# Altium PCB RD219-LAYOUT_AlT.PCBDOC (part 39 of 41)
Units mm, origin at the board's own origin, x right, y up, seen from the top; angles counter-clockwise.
Board outline 209.75 x 159.97 mm, 2 copper layers (TOP, BOTTOM), stack 0 mm thick; 398 components, 199 nets, 1469 pads, 0 vias.
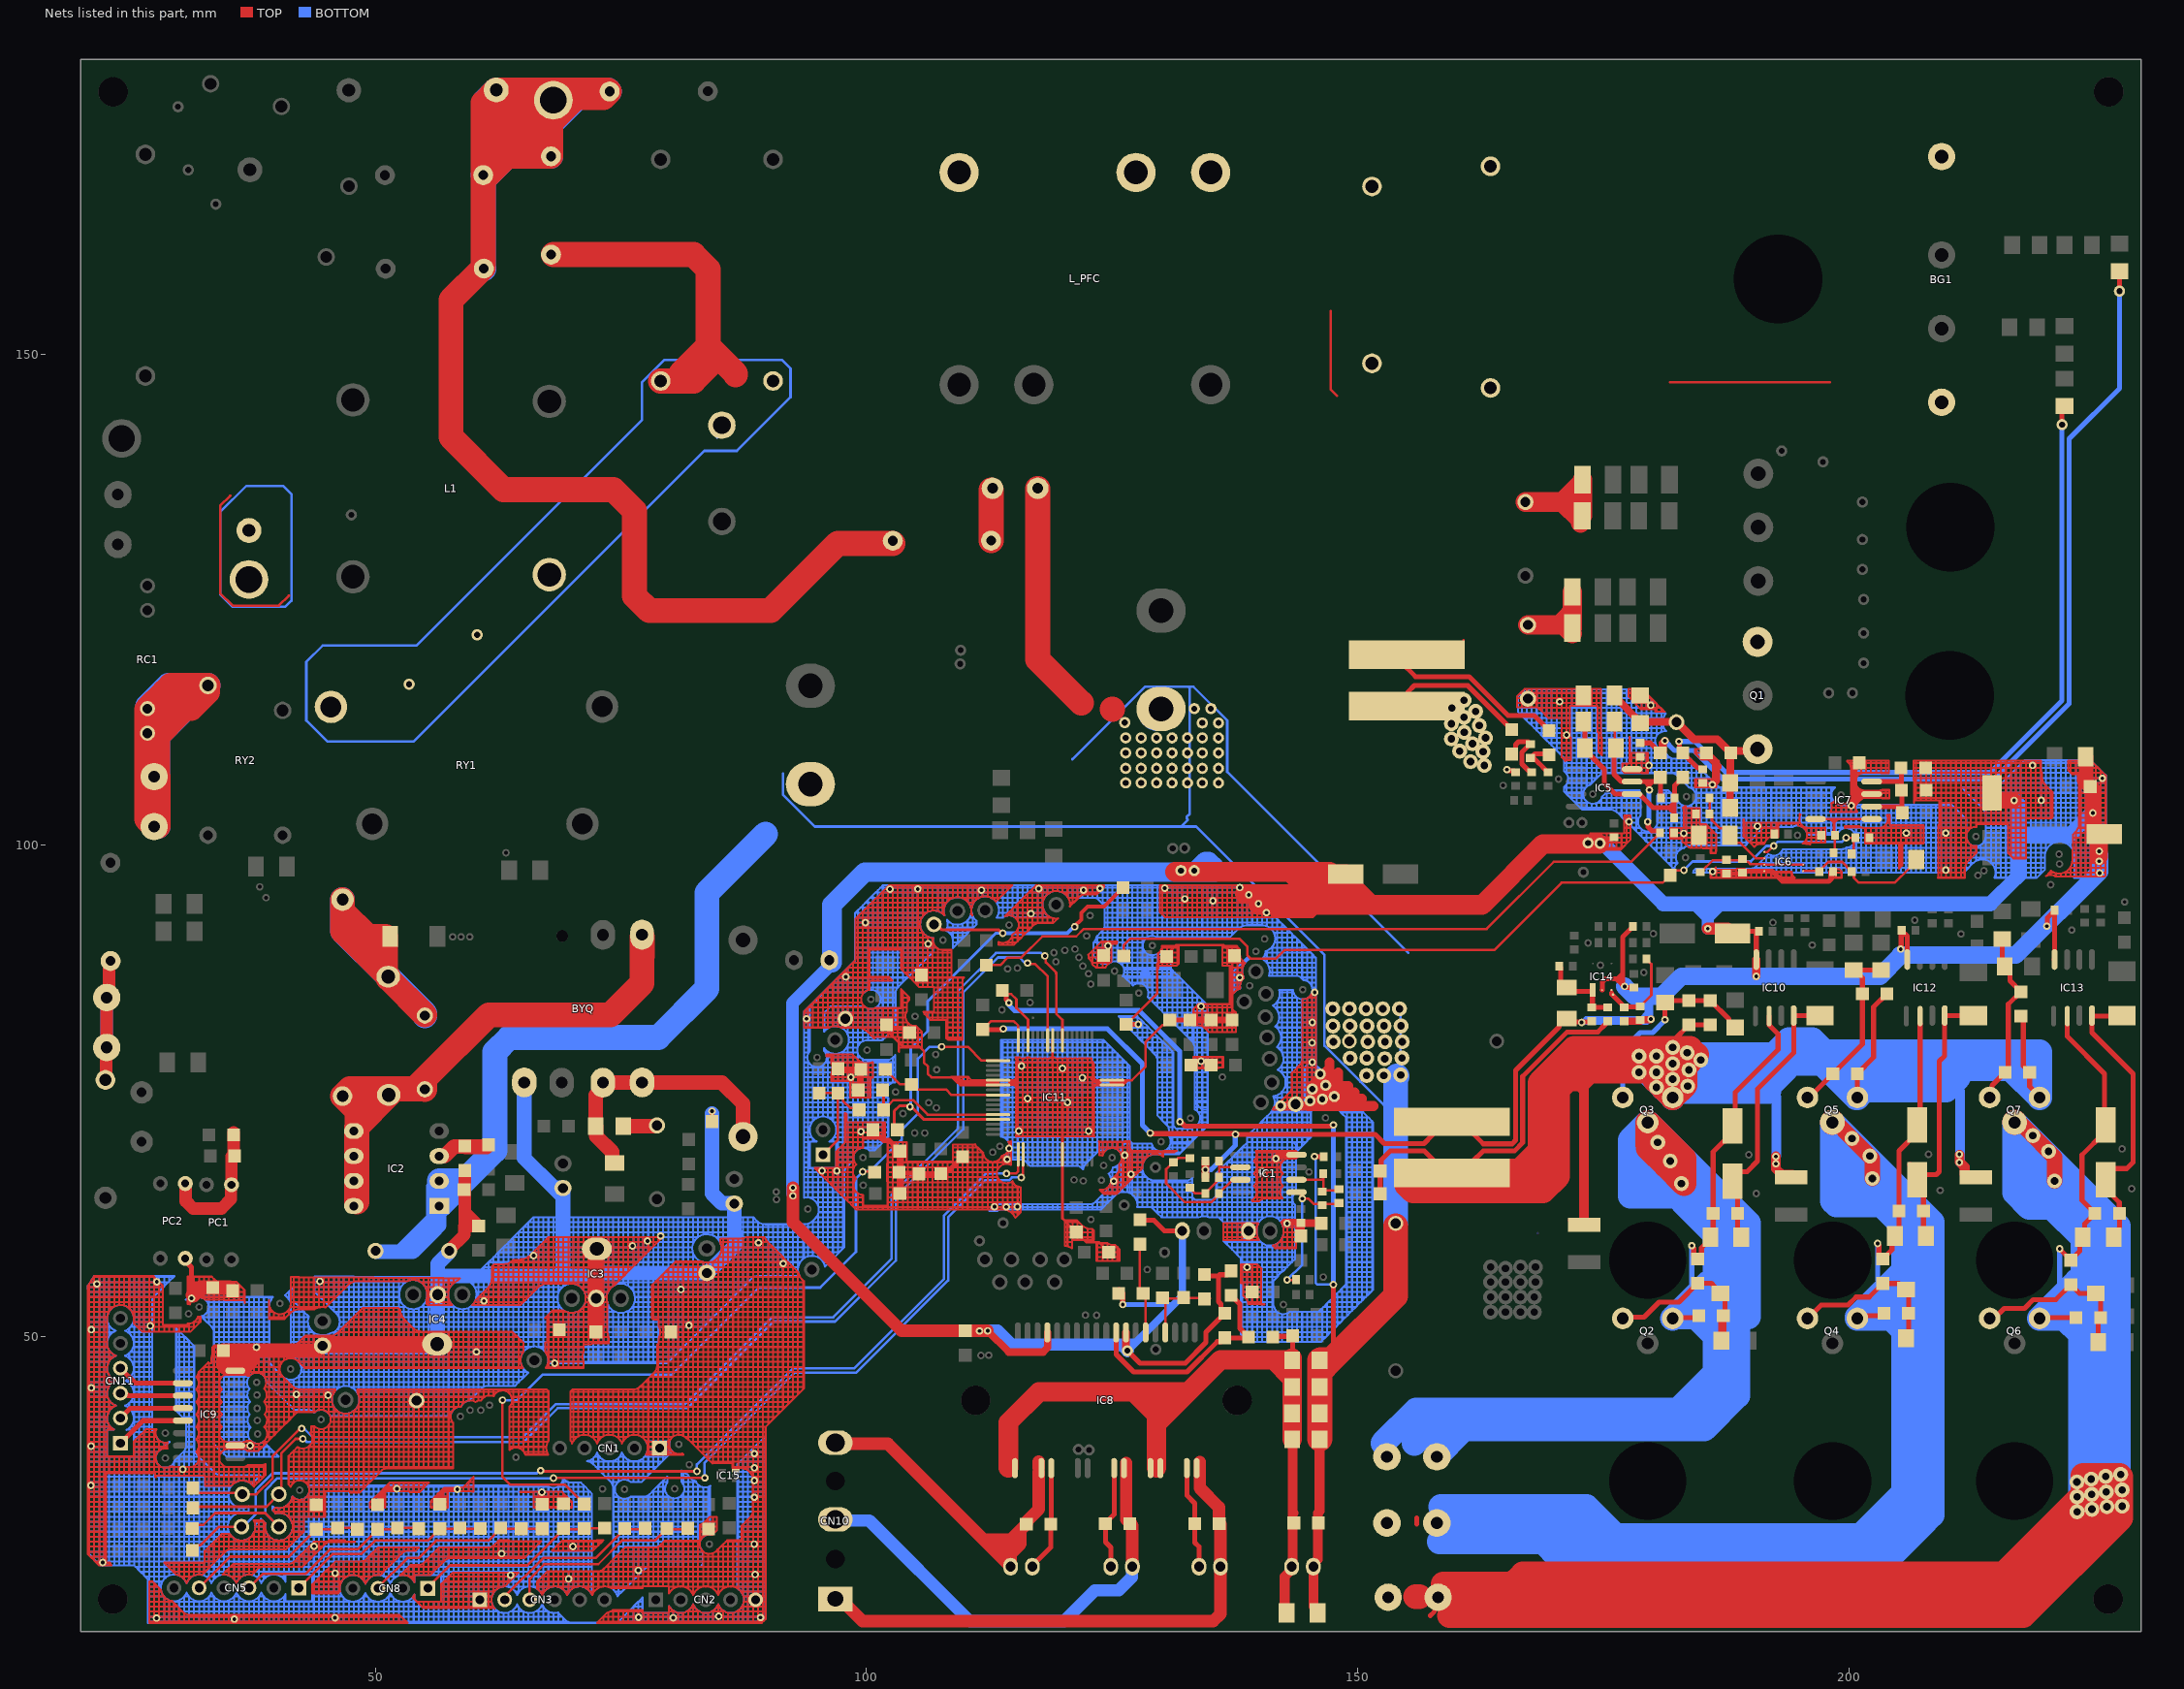
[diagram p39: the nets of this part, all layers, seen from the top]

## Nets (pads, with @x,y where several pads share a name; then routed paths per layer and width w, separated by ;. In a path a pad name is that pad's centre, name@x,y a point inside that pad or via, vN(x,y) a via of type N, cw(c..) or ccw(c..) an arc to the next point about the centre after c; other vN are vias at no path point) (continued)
GND: (continued)
  BOTTOM w1.2: 184.465,94.051 184.465,93.803 185.624,92.644 ; pad.@185.624,91.535 185.624,92.644 ; 185.624,93.908 185.624,92.644 ; 186.878,94.051 186.878,93.898 185.624,92.644
  BOTTOM w1.27: pad.@92.479,64.572 92.479,83.975 EC4.2@96.378,87.874 ; pad.@111.499,50.588 pad.@112.348,50.588 ; pad.@112.327,50.596 113.356,50.596 114.742,49.21 125.918,49.21 pad.@126.553,48.575
  BOTTOM w1.5: EC6.2@44.638,49.083 44.742,49.083 44.765,49.06 44.869,48.956 55.402,48.956 55.433,48.987 55.707,49.261 55.941,49.261 IC4.4@56.3,49.261 56.333,49.294 56.333,49.464 56.333,49.972 56.333,50.48 56.333,50.988 56.333,51.496 56.333,52.004 56.333,52.512 56.333,53.02 56.333,53.528 56.333,54.036 56.333,54.261 IC4.2@56.362,54.29 56.362,54.544 56.362,55.052 56.362,55.56 56.362,56.068 ; C63.1@50.032,58.735 50.122,58.645 52.766,58.645 ; C63.2@57.532,58.735 57.532,58.599 56.362,57.429 56.362,56.08 56.362,56.068 ; BYQ.5@65.161,75.88 65.161,68.184 68.191,65.154 ; IC3.2@72.491,53.909 72.52,53.938 72.52,54.036 72.52,54.544 72.52,55.052 72.52,55.56 72.52,56.068 72.52,56.195 ; IC3.4@72.553,58.938 72.52,58.905 72.52,58.608 72.52,58.1 72.52,57.592 72.52,57.084 72.52,56.576 72.52,56.195 ; pad.@84.262,72.705 84.262,64.577 85.268,63.572 86.512,63.572 EC18.2@86.541,63.543 86.541,62.164 86.541,61.656 86.541,61.148 86.541,60.691 86.592,60.64 86.592,60.132 86.592,59.624 86.592,59.263 86.445,59.116 86.421,59.092 85.937,58.608 85.913,58.584 85.781,58.453 85.429,58.1 85.405,58.076 84.921,57.592 84.897,57.569 84.413,57.084 84.389,57.061 84.29,56.962 83.905,56.576 83.881,56.553 83.818,56.489 EC5.2@83.754,56.489 83.373,56.489 82.865,56.489 82.357,56.489 81.849,56.489 81.341,56.489 80.833,56.489 80.325,56.489 79.817,56.489 79.309,56.489 78.801,56.489 78.293,56.489 77.785,56.489 77.277,56.489 76.769,56.489 76.261,56.489 75.753,56.489 75.245,56.489 74.737,56.489 74.229,56.489 73.721,56.489 73.213,56.489 72.814,56.489 72.705,56.38 72.52,56.195 ; EC4.2@96.229,87.747 96.229,87.847 EC4.2@96.327,87.945 ; pad.@173.432,100.248 174.629,100.248 pad.@174.657,100.219 174.916,100.219 181.084,94.051 184.465,94.051 185.481,94.051 186.878,94.051 214.386,94.051 217.044,96.708 217.295,96.959 217.295,97.216 217.295,97.724 217.295,98.232 217.295,98.74 217.295,99.248 217.295,99.756 217.295,100.264 217.295,100.772 217.295,101.153 ; pad.@216.85,104.582 216.977,104.455 217.104,104.328 217.295,104.137 217.295,103.82 217.295,103.312 217.295,102.804 217.295,102.296 217.295,101.788 217.295,101.28 217.295,101.153 ; pad.@224.851,103.439 224.724,103.312 224.597,103.185 224.216,102.804 224.089,102.677 223.708,102.296 223.581,102.169 223.2,101.788 223.073,101.661 222.692,101.28 222.565,101.153 222.057,101.153 221.549,101.153 221.041,101.153 220.533,101.153 220.025,101.153 219.517,101.153 219.009,101.153 218.501,101.153 217.993,101.153 217.485,101.153 217.295,101.153 ; 52.766,58.645 53.819,58.645 55.941,60.767 ; 52.766,58.645 52.766,58.862 55.941,62.037 ; 55.941,60.767 56.513,61.339 IC2.1@56.513,63.307 IC2.2@56.513,65.847 56.34,65.847 56.294,65.801 56.294,65.628 55.941,65.275 55.941,62.037 ; 55.941,60.767 55.941,62.037 ; 56.362,56.068 56.374,56.08 56.489,56.195 60.132,56.195 60.513,56.195 61.021,56.195 61.529,56.195 62.037,56.195 62.545,56.195 63.053,56.195 63.561,56.195 64.069,56.195 64.577,56.195 65.085,56.195 65.593,56.195 66.101,56.195 66.609,56.195 67.117,56.195 67.625,56.195 68.133,56.195 68.641,56.195 69.022,56.195 ; 68.191,65.154 69.076,65.154 EC3.2@69.105,65.125 69.105,64.24 ; 68.191,65.154 68.663,64.682 69.105,64.24 ; 69.022,56.195 69.149,56.195 69.657,56.195 70.165,56.195 70.673,56.195 71.181,56.195 71.689,56.195 72.197,56.195 72.52,56.195 ; 69.022,56.195 69.105,56.278 69.105,56.576 69.105,57.084 69.105,57.592 69.105,58.1 69.105,58.608 69.105,59.116 69.105,59.624 69.105,60.132 69.105,60.64 69.105,61.148 69.105,61.656 69.105,62.164 69.105,64.24
  BOTTOM w1.8: pad.@177.158,85.649 178.163,84.643 179.766,84.643 180.909,84.643 182.941,86.675 pad.@190.561,86.675 203.134,86.675 205.187,88.728 ; 205.187,88.834 216.977,88.834 225.486,97.343 225.486,97.851 225.486,98.232 225.486,98.74 225.486,98.994
  BOTTOM w2: EC4.2@96.476,88.072 96.476,93.936 99.824,97.283 pad.@133.411,97.283 ; pad.@133.411,97.283 135.443,97.283 135.443,97.724 134.808,98.359 134.487,98.359 pad.@133.411,97.283
  BOTTOM w2.54: IC2.1@56.513,63.307 59.053,65.847 ; IC2.2@56.513,65.847 59.053,65.847 ; 89.723,101.153 83.754,95.184 83.754,85.405 78.801,80.452 63.652,80.452 62.164,78.964 62.164,68.958 59.053,65.847 ; EC2.2@94.045,106.233 EC2.2@94.295,106.233 ; C90.1@153.858,61.536 153.858,76.388 pad.@153.871,76.4 ; pad.@153.982,76.511 pad.@153.985,76.508
  BOTTOM w4: EC2.2@94.295,106.233 EC2.2@94.391,106.329 ; EC1.2@129.636,113.655 129.867,113.886 EC1.2@129.982,113.886
HVMOS: C88.1 IC11.28 R142.2 | length 14.1
  TOP w0.254: C88.1@101.661,75.118 101.737,75.042 R142.2@101.737,73.086 ; R142.2@102.172,73.521 102.718,74.067 102.775,74.067 102.784,74.076 104.735,74.076 106.208,72.603 109.544,72.603 109.547,72.606 IC11.28@113.387,72.606
IAC_AD: C12.1 IC11.29 pad.@104.426,73.39 pad.@113.863,91.056 pad.@121.191,91.719 R9.2 TP5.1 | length 57.3
  TOP w0.3: C12.1@103.134,71.054 102.825,71.364 102.825,72.973 103.359,73.507 103.659,73.507 103.688,73.478 104.338,73.478 pad.@104.426,73.39 ; pad.@104.519,73.444 105.857,72.106 IC11.29@113.387,72.106 ; TP5.1@106.858,91.966 107.113,91.966 107.684,91.395 113.457,91.395 113.796,91.056 pad.@113.863,91.056
  TOP w0.4: pad.@121.191,91.719 121.191,91.78 121.854,92.443 121.854,93.152 122.489,93.787 124.191,93.787 R9.2@126.096,95.692
  BOTTOM w0.3: pad.@104.426,73.39 104.508,73.472 104.508,79.362 106.233,81.087 106.233,84.135 113.154,91.056 pad.@113.863,91.056
  BOTTOM w0.4: pad.@113.863,91.056 113.879,91.072 120.451,91.072 121.098,91.719 pad.@121.191,91.719
IGBT: C73.1 IC11.17 pad.@62.946,43.546 pad.@99.611,66.795 pad.@107.639,79.506 R79.2 | length 93.4
  TOP w0.254: pad.@62.946,43.546 62.946,35.728 63.734,34.94 69.31,34.94 R79.2@71.268,32.982 ; pad.@99.611,66.795 100.763,66.795 C73.1@100.823,66.736 C73.1@100.3,66.213 ; pad.@107.639,79.506 110.306,79.506 111.706,78.106 IC11.17@113.387,78.106
  BOTTOM w0.254: pad.@62.946,43.546 64.422,43.546 67.042,46.166 80.219,46.166 89.054,55.001 95.284,55.001 98.928,58.645 98.928,66.113 pad.@99.611,66.795 99.66,66.845 100.373,66.845 103.566,70.038 103.566,71.055 105.217,72.706 105.217,78.293 106.421,79.497 107.63,79.497 pad.@107.639,79.506
IGBT-Driver: C9.2 Q1.1 R43.1 R44.1 R135.1 TP10.1 ZD8.2 | length 23.8
  TOP w0.762: ZD8.2@176.137,115.25 176.137,115.05 176.556,114.631 176.68,114.631 177.496,113.815 177.496,113.791 178.231,113.056 178.231,112.872 178.65,112.453 R135.1@178.75,112.453 ; R44.1@187.891,103.693 187.89,103.694 187.891,103.696 R44.1@187.891,103.82 R43.1@187.891,106.36 ; R43.1@187.891,106.46 R43.1@187.891,106.36 ; R43.1@187.893,106.358 R43.1@187.891,106.36 ; C9.2@187.97,109.408 C9.2@187.972,109.409 ; Q1.1@190.688,109.257 Q1.1@190.688,109.789
  TOP w0.8: R135.1@178.75,112.453 178.88,112.583 181.163,112.583 ; 181.203,112.583 182.433,112.583 184.211,110.805 186.573,110.805 C9.2@187.97,109.408 187.931,109.368 187.931,106.4 R43.1@187.891,106.36 ; C9.2@187.972,109.409 188.161,109.599 190.498,109.599 Q1.1@190.688,109.789
IV+: C59.2 C94.2 C96.2 C101.2 C102.2 C103.2 pad.@178.623,76.896 pad.@178.623,78.547 pad.@180.401,75.372 pad.@180.401,76.896 pad.@180.401,78.547 pad.@182.043,76.203 pad.@182.052,77.785 pad.@182.052,79.436 pad.@183.523,78.888 pad.@183.576,75.499 pad.@183.703,77.15 pad.@184.913,78.156 pad.@192.545,68.338 pad.@192.553,67.597 pad.@211.223,68.554 pad.@211.226,67.742 Q3.3 Q5.3 Q7.3 R95.1 R99.1 R100.1 R103.1 R124.2 R131.2 R143.2 | length 359.5
  TOP w0.254: R100.1@152.277,64.548 R100.1@152.28,64.551
  TOP w0.508: R100.1@152.28,64.551 152.28,66.86 R99.1@152.283,66.863 152.375,66.955 152.375,67.977 153.312,68.915 156.759,68.915 R95.1@157.859,67.816 ; R95.1@161.732,67.879 162.748,68.895 165.94,68.895 166.782,69.737 166.782,76.479 171.317,81.014 174.425,81.014 175.252,81.842 175.252,81.957 175.398,82.103 R103.1@175.448,82.103 ; C101.2@171.639,61.843 172.085,61.397 C101.2@173.035,61.397 ; 173.035,76.134 173.924,77.023 ; pad.@182.052,78.384 182.062,78.374 pad.@182.367,78.374 ; pad.@182.052,79.436 182.246,79.63 182.246,80.265 C59.2@183.703,81.722 R124.2@185.862,81.722 ; Q5.3@200.848,74.348 C94.2@200.848,76.769 202.499,78.42 202.499,83.551 R131.2@203.845,84.897 R131.2@203.909,84.834 ; C103.2@212.028,66.345 C103.2@212.913,66.345 ; R143.2@217.739,82.738 217.739,77.531 C96.2@218.374,76.896 218.374,75.484 219.39,74.468 Q7.3@219.39,74.348 ; R95.1@157.181,66.676 R95.1@159.573,66.676 159.408,67.208 R95.1@157.181,66.676
  TOP w1: 170.316,75.193 170.622,75.499 172.527,75.499 ; C101.2@173.035,61.397 173.035,74.991 ; 173.035,76.134 173.035,75.499 ; 173.924,77.023 173.924,76.388 173.035,75.499 ; pad.@192.553,68.338 pad.@192.553,67.597 192.553,67.091 193.162,66.482 C102.2@194.244,66.482 ; pad.@211.262,68.514 211.262,67.774 211.763,67.273 211.763,66.545 211.963,66.345 C103.2@212.028,66.345 ; 172.527,75.499 173.035,75.499 ; 172.527,75.499 173.035,74.991 ; 173.035,74.991 173.035,75.499
  TOP w2.54: R95.1@155.001,65.466 155.636,64.831 166.379,64.831 ; R95.1@159.573,66.676 159.753,66.856 166.518,66.856 168.557,68.895 168.557,75.847 172.019,79.309 179.639,79.309 ; 169.292,74.169 170.316,75.193 170.316,68.768 ; 170.622,75.499 172.146,77.023 173.924,77.023 179.504,77.023 ; pad.@180.207,76.194 180.715,75.686 181.12,75.28 Q3.3@182.052,74.348 183.29,75.586 pad.@183.29,77.499 ; pad.@182.043,76.203 pad.@182.043,76.252 ; 166.379,64.831 170.316,68.768 ; 166.379,64.831 168.828,64.831 170.316,66.319 170.316,68.768 ; 179.639,79.309 pad.@180.401,78.547 182.043,76.905 pad.@182.043,76.252 ; 179.639,79.309 pad.@181.671,79.309 ; pad.@181.671,79.309 183.83,79.309 184.465,78.674 pad.@183.29,77.499 ; pad.@181.671,79.309 183.29,77.69 pad.@183.29,77.499 ; pad.@182.043,76.252 pad.@183.29,77.499
  BOTTOM w0.508: 191.835,74.991 191.835,74.987 192.422,74.4
  BOTTOM w1: pad.@192.545,68.338 pad.@192.563,68.338 ; pad.@192.563,67.628 pad.@192.563,68.338 ; 192.593,74.356 192.593,68.403 192.563,68.373 pad.@192.563,68.338 ; pad.@211.295,67.742 211.295,74.958 211.135,75.118 211.135,76.388 212.024,77.277
  BOTTOM w2.54: pad.@180.401,76.896 182.306,76.896 182.521,76.681 182.878,76.325 183.453,75.749 184.85,77.146 ; 185.646,77.942 185.387,77.683 184.85,77.146 ; 199.32,77.146 199.642,77.468 200.848,76.261 ; 211.135,76.388 209.865,75.118 201.618,75.118 Q5.3@200.848,74.348 ; 184.85,77.146 192.949,77.146 193.21,76.885 ; 192.339,78.674 194.999,78.674 ; 192.339,78.674 193.863,80.198 196.268,80.198 197.502,78.964 ; 192.339,78.674 180.147,78.674 179.385,77.912 179.385,77.015 181.12,75.28 Q3.3@182.052,74.348 182.695,74.991 191.835,74.991 191.835,75.51 193.21,76.885 ; 193.21,76.885 194.177,77.852 ; 194.177,77.852 197.221,77.852 200.725,74.348 Q5.3@200.848,74.348 ; 194.177,77.852 194.999,78.674 ; 194.999,78.674 197.792,78.674 ; 197.502,78.964 219.39,78.964 219.39,76.515 ; 197.502,78.964 197.792,78.674 ; 197.792,78.674 217.231,78.674 218.565,77.341 ; Q5.3@200.848,74.348 200.848,76.261 ; 200.848,76.261 201.229,76.261 202.245,77.277 212.024,77.277 216.461,77.277 ; 216.461,77.277 Q7.3@219.39,74.348 219.39,76.515 ; 216.461,77.277 218.501,77.277 218.565,77.341 ; 218.565,77.341 219.39,76.515
LED1: IC11.33 pad.@66.833,36.376 pad.@82.737,36.311 pad.@114.245,66.61 R67.2 TP12.1 | length 107.4
  TOP w0.254: R67.2@31.379,28.255 31.892,28.768 32.197,28.768 34.097,30.668 TP12.1@36.383,30.668 ; pad.@66.833,36.376 66.909,36.3 82.726,36.3 pad.@82.737,36.311 ; pad.@114.245,66.61 115.189,66.61 115.437,66.858 IC11.33@115.437,68.556
  BOTTOM w0.254: TP12.1@36.423,30.541 37.844,31.962 37.844,34.415 39.532,36.103 66.43,36.103 66.704,36.376 pad.@66.833,36.376 ; pad.@82.737,36.311 82.737,37.003 88.63,42.897 92.503,46.77 98.75,46.77 107.884,55.904 107.884,62.346 112.148,66.61 pad.@114.245,66.61
LED2: IC11.34 pad.@68.133,35.618 pad.@83.551,35.642 pad.@115.751,66.202 R68.2 TP13.1 | length 111.6
  TOP w0.254: R68.2@31.367,30.478 31.741,30.852 32.503,30.852 33.716,32.065 38.796,32.065 TP13.1@40.193,30.668 ; pad.@68.133,35.618 68.145,35.63 83.539,35.63 pad.@83.551,35.642 ; pad.@115.751,66.202 115.751,66.34 115.937,66.526 IC11.34@115.937,68.556
  BOTTOM w0.254: TP13.1@40.193,30.668 38.796,32.065 38.796,34.351 40.04,35.595 68.11,35.595 pad.@68.133,35.618 ; pad.@83.551,35.642 83.5,35.694 83.5,37.156 89.062,42.718 92.682,46.338 98.929,46.338 108.316,55.725 108.316,62.167 112.073,65.924 114.529,65.924 114.807,66.202 pad.@115.751,66.202
LED3: IC11.10 pad.@40.701,33.97 pad.@42.625,39.609 pad.@116.388,88.026 R69.2 TP14.1 | length 132.1
  TOP w0.254: R69.2@31.43,32.573 31.557,32.7 38.923,32.7 TP14.1@40.193,33.97 40.447,34.224 40.447,38.161 41.895,39.609 pad.@42.625,39.609 ; pad.@116.388,88.026 116.471,87.943 117.15,87.943 118.437,86.656 IC11.10@118.437,80.156
  BOTTOM w0.254: pad.@42.625,39.609 42.723,39.609 43.028,39.304 65.133,39.304 68.562,42.733 81.746,42.733 90.558,51.545 96.788,51.545 102.98,57.737 102.98,64.245 109.853,71.118 109.853,85.064 113.381,88.592 115.574,88.592 116.043,88.123 116.291,88.123 pad.@116.388,88.026
LED4: IC11.7 pad.@42.513,40.658 pad.@118.147,88.757 R70.2 TP15.1 | length 133.3
  TOP w0.254: R70.2@31.43,34.605 31.938,34.097 36.336,34.097 TP15.1@36.463,33.97 37.907,33.97 39.558,35.621 39.558,37.872 42.247,40.561 42.415,40.561 pad.@42.513,40.658 ; pad.@118.147,88.757 118.245,88.66 118.245,88.101 119.301,87.045 119.301,86.942 119.303,86.94 119.303,82.876 119.937,82.242 IC11.7@119.937,80.156
  BOTTOM w0.254: pad.@42.513,40.658 42.61,40.561 42.86,40.561 43.66,39.761 64.979,39.761 68.375,43.157 81.552,43.157 90.372,51.977 96.609,51.977 102.548,57.916 102.548,64.424 109.309,71.185 109.309,85.179 113.179,89.049 117.745,89.049 118.037,88.757 pad.@118.147,88.757
NetAC-L_1: AC_L.1 F1.1 | length 54.2
  TOP w0.254: 35.24,135.57 34.224,134.554 34.224,125.664 35.494,124.394 40.193,124.394 41.209,125.41
  BOTTOM w0.254: 34.224,125.537 35.494,124.267 40.828,124.267 41.463,124.902 41.463,135.697 41.485,135.719 40.618,136.586 36.891,136.586 34.224,133.919 34.224,125.537
NetBG1_1: BG1.1 C8.1 L_PFC.1 L_PFC.2 L_PFC.3 Z2.1
NetBG1_4: BG1.4 C8.2 R1.2 R2.1 Z2.2 | length 50.9
  TOP w0.254: 147.254,154.366 147.254,146.365 147.889,145.73 ; R1.2@155.065,119.328 R1.2@155.711,119.328 ; R1.2@159.258,119.39 159.457,119.39 160.778,120.711 160.778,120.859 ; C8.2@163.51,146.545 C8.2@163.838,146.873 ; 181.798,147.127 198.054,147.127
  TOP w0.5: R1.2@154.979,118.066 155.876,117.169 161.337,117.169 165.288,113.218 167.955,113.218 R2.1@169.479,111.694 ; R1.2@155.005,119.388 R1.2@155.065,119.328 ; R1.2@155.711,119.39 R1.2@158.299,119.39 ; R1.2@159.258,119.39 R1.2@158.299,119.39 ; R1.2@159.446,118.243 R1.2@158.299,119.39
NetBYQ_1: BYQ.1 C25.2 D6.2 IC2.5 IC2.6 IC2.7 IC2.8 R19.2 | length 59
  TOP w2.54: IC2.8@48.103,63.702 48.103,65.847 IC2.5@48.103,71.344 ; IC2.5@48.175,71.183 IC2.5@48.175,71.416 ; BYQ.1@77.163,90.663 77.163,88.751 77.15,88.738 77.15,85.951 73.95,82.751 61.546,82.751 55.052,76.257 ; IC2.5@48.175,71.416 D6.2@51.369,74.61 D6.2@51.988,75.229 ; IC2.5@48.175,71.416 48.175,72.978 R19.2@46.67,74.483 47.416,75.229 D6.2@51.988,75.229 ; D6.2@51.988,75.229 54.025,75.229 ; 54.025,75.229 55.001,75.229 C25.2@55.052,75.178 55.052,76.257 ; 54.025,75.229 54.513,75.717 55.052,76.257
NetBYQ_7: BYQ.7 BYQ.8 D4.1 D5.1 R134.2 | length 27.6
  TOP w1.27: BYQ.8@77.137,75.867 BYQ.8@77.15,75.88
  TOP w1.5: D5.1@74.356,67.879 74.106,68.129 74.106,68.803 72.498,70.411 72.498,71.385 R134.2@72.448,71.435 72.448,74.593 73.162,75.308 BYQ.7@73.162,75.855 73.175,75.867 BYQ.8@77.137,75.867 ; BYQ.8@77.15,75.88 85.278,75.88 87.437,73.721 D4.1@87.437,70.358
NetC2_1: C2.1 C6.2 C7.1 L1.4 pad.@53.446,116.399 pad.@60.367,121.42 pad.@84.784,141.512 PTC.1 RY1.2 | length 181
  TOP w2.54: C6.2@68.148,160.114 82.393,160.114 83.881,158.626 83.881,150.81 ; C2.1@79.055,147.254 81.087,147.254 ; 86.675,147.889 86.675,148.016 83.881,150.81 ; 81.087,147.254 82.393,147.254 83.881,148.742 83.881,150.81 ; 81.087,147.254 81.087,148.016 83.881,150.81
  BOTTOM w0.254: PTC.1@84.854,141.643 85.549,142.338 85.696,142.338 85.696,142.485 PTC.1@86.454,143.243 ; 42.987,112.71 45.146,110.551 53.909,110.551 83.5,140.142 86.802,140.142 92.263,145.603 92.263,148.524 91.374,149.413 79.436,149.413 77.15,147.127 77.15,143.317 54.163,120.33 44.638,120.33 42.987,118.679 42.987,112.71
NetC3_1: C3.1 C4.1 C5.1 C6.1 C61.1 GND_EARTH.1 pad.@62.307,176.87 SA1.1 | length 249.1
  TOP w2.54: C3.1@60.903,158.693 57.719,155.509 57.719,141.539 63.053,136.205 74.229,136.205 76.388,134.046 76.388,125.374 77.876,123.886 90.231,123.886 97.076,130.731 C61.1@102.677,130.731 ; C3.1@60.988,158.759 60.988,168.205 C4.1@60.99,168.207 60.99,175.553 pad.@62.307,176.87 ; C4.1@61.496,168.222 63.082,169.807 63.082,170.421 ; 62.307,170.114 pad.@62.307,176.87 ; GND_EARTH.1@67.879,175.575 67.866,175.562 67.866,173.543 ; pad.@62.307,176.87 pad.@63.082,176.096 ; pad.@62.307,176.87 73.696,176.87 C5.1@73.848,176.718 73.226,176.096 70.419,176.096 ; 63.082,170.421 63.388,170.114 64.831,170.114 ; 63.082,170.421 pad.@63.082,176.096 ; pad.@63.082,176.096 64.704,176.096 ; 64.704,176.096 GND_EARTH.1@66.228,176.096 ; 64.704,176.096 64.704,170.241 64.831,170.114 ; 64.831,170.114 66.228,170.114 ; 66.228,170.114 C6.1@67.879,170.114 67.879,171.738 67.866,171.752 ; 66.228,170.114 67.054,170.94 67.866,171.752 ; 66.228,170.114 GND_EARTH.1@66.228,176.096 ; GND_EARTH.1@66.228,176.096 67.866,176.096 GND_EARTH.1@68.133,175.829 ; 67.866,171.752 67.866,173.543 ; 67.866,173.543 69.142,174.82 70.419,176.096 ; GND_EARTH.1@68.133,175.829 68.511,175.829 GND_EARTH.1@68.778,176.096 ; GND_EARTH.1@68.133,175.829 68.4,176.096 GND_EARTH.1@68.778,176.096 ; GND_EARTH.1@68.778,176.096 70.419,176.096
  BOTTOM w2.54: C4.1@60.99,168.207 C4.1@61.021,168.176 ; C3.1@61.054,158.693 61.021,158.727 C4.1@61.021,168.176 ; 61.496,171.602 61.496,168.222 63.592,170.318 ; C4.1@61.021,168.176 61.021,175.584 pad.@62.307,176.87 ; pad.@62.307,176.87 62.981,176.197 64.323,176.197 ; pad.@62.307,176.87 62.307,171.602 63.592,170.318 ; pad.@62.307,176.87 73.696,176.87 C5.1@73.848,176.718 71.181,176.718 71.054,176.591 ; 63.592,170.318 64.323,171.049 64.323,176.197 ; 63.592,170.318 63.795,170.114 65.72,170.114 ; 64.323,176.197 GND_EARTH.1@66.777,176.197 ; 65.72,170.114 C6.1@67.879,170.114 67.879,173.543 ; 65.72,170.114 66.777,171.171 GND_EARTH.1@66.777,176.197 ; GND_EARTH.1@66.777,176.197 66.878,176.096 67.866,176.096 GND_EARTH.1@68.133,175.829 ; 67.879,173.543 68.006,173.543 71.054,176.591 ; 67.879,173.543 67.879,175.575 GND_EARTH.1@68.133,175.829 ; GND_EARTH.1@68.133,175.829 68.511,175.829 69.273,176.591 71.054,176.591
NetC10_1: C10.1 R38.1 R40.1 | length 15.2
  TOP w2: C10.1@167.066,134.935 170.846,134.935 ; R38.1@172.598,134.924 172.587,134.935 170.846,134.935 ; R38.1@172.678,132.829 172.678,133.103 170.846,134.935 ; R38.1@172.856,133.538 172.869,133.551 R40.1@172.869,136.958 ; 170.846,134.935 R40.1@172.869,136.958 ; R40.1@172.869,136.958 172.882,136.971 R40.1@172.882,137.221 172.869,137.208 R40.1@172.869,136.958
NetC11_1: C11.1 R3.2 R4.1 | length 6.6
  TOP w0.508: R3.2@165.669,109.281 166.058,109.67 166.058,110.253 166.356,110.551 167.32,110.551 C11.1@167.574,110.297 ; C11.1@167.524,110.297 166.956,109.729 166.945,109.729 166.692,109.476 166.692,108.289 167.394,107.587 167.555,107.587 R4.1@167.701,107.441
NetC11_2: C11.2 R2.2 R5.1 | length 4.5
  TOP w0.5: C11.2@167.574,108.897 167.624,108.897 168.036,109.309 169.375,109.309 R2.2@169.479,109.205
  TOP w0.508: C11.2@167.574,108.897 167.72,108.751 168.04,108.751 168.399,108.392 168.401,108.392 169.156,107.637 169.156,107.587 169.302,107.441 R5.1@169.352,107.441
NetC13_2: C13.2 D7.2 IC6.2 R10.1 | length 9.4
  TOP w0.254: R10.1@185.8,104.836 C13.2@185.8,103.185 186.046,102.939 186.046,102.55 186.843,101.753 187.202,101.753 D7.2@187.875,101.08 ; D7.2@187.875,101.026 187.875,100.94 188.548,100.267 188.907,100.267 190.49,98.684 IC6.2@191.38,98.684
NetC14_2: C14.2 IC6.3 IC6.6 R13.1 R14.2 | length 11.2
  TOP w0.254: R13.1@184.973,97.34 186.119,98.486 187.462,98.486 R14.2@187.506,98.53 187.55,98.486 189.039,98.486 C14.2@189.169,98.616 189.442,98.343 189.688,98.343 189.924,98.107 191.307,98.107 IC6.3@191.38,98.034 IC6.6@195.33,98.034
NetC17_2: C17.2 IC6.1 pad.@183.195,97.47 pad.@192.336,99.942 pad.@199.705,100.772 pad.@200.656,100.772 R15.1 R17.1 R18.1 | length 85.4
  TOP w0.254: R17.1@126.174,88.726 126.174,89.85 126.809,90.485 137.983,90.485 138.745,89.723 138.745,88.834 139.126,88.453 141.666,88.453 142.555,89.342 163.891,89.342 170.749,96.2 181.036,96.2 R18.1@181.798,96.962 182.306,97.47 pad.@183.195,97.47 ; IC6.1@191.38,99.334 191.705,99.334 192.313,99.942 pad.@192.336,99.942 ; pad.@199.705,100.772 C17.2@200.435,100.772 ; R15.1@200.275,99.121 200.467,99.313 200.467,100.583 C17.2@200.656,100.772 C17.2@200.435,100.772 ; C17.2@200.467,100.804 C17.2@200.435,100.772
  BOTTOM w0.254: pad.@183.195,97.47 184.084,98.359 190.002,98.359 191.585,99.942 pad.@192.336,99.942 ; pad.@192.322,99.956 192.709,100.342 199.275,100.342 pad.@199.705,100.772
NetC18_2: C18.2 D8.1 IC6.5 R16.2 | length 15
  TOP w0.254: IC6.5@195.33,97.384 196.932,97.384 C18.2@196.973,97.343 196.973,97.393 197.246,97.666 197.249,97.666 197.899,98.316 199.29,98.316 200.213,97.393 R16.2@200.213,97.293 ; R16.2@200.275,97.343 200.494,97.124 200.494,96.681 200.975,96.2 204.663,96.2 206.16,97.697 206.833,98.37 D8.1@206.833,98.57 ; D8.1@206.779,98.624 D8.1@206.96,98.805 ; D8.1@206.869,98.534 206.96,98.624 D8.1@206.96,98.805 ; D8.1@206.96,98.824 D8.1@206.96,98.805 ; D8.1@207,98.792 D8.1@207.091,98.882 ; D8.1@207.037,98.882 D8.1@206.96,98.805
NetC20_2: C20.2 IC7.2 IC7.4 R41.2 R42.2 | length 11.7
  TOP w0.254: R41.2@204.897,102.789 R41.2@205.42,103.312 R41.2@205.382,103.35
  TOP w0.5: IC7.4@202.301,106.487 205.318,106.487 ; IC7.2@202.32,103.928 IC7.2@202.301,103.947 R41.2@205.293,103.947 ; R41.2@205.039,103.693 R41.2@205.293,103.693 ; R42.2@205.293,107.884 205.318,107.859 205.318,106.487 ; R41.2@205.382,103.35 205.382,105.56 C20.2@205.344,105.598 205.318,105.623 205.318,106.487
NetC22_1: C22.1 IC2.3 R21.1 | length 5.1
  TOP w1.5: IC2.3@56.513,68.387 56.532,68.406 57.103,68.406 58.046,69.349 C22.1@59.062,69.349 ; C22.1@59.185,69.334 R21.1@61.333,69.334
NetC25_1: C25.1 D3.1 D6.1 R19.1 | length 41.2
  TOP w2.54: R19.1@46.67,94.483 46.67,93.274 ; D6.1@51.196,86.636 D6.1@51.324,86.636 ; D6.1@51.324,86.466 C25.1@55.052,82.738 ; 46.67,93.274 49.21,90.734 ; 46.67,93.274 46.67,91.29 47.226,90.734 ; 47.226,90.734 51.022,86.938 51.022,90.734 49.21,90.734 ; 47.226,90.734 49.21,90.734
  BOTTOM w2.54: R19.1@46.67,94.483 46.67,91.29 D6.1@51.324,86.636 55.052,82.908 C25.1@55.052,82.678
NetC26_2: C26.2 pad.@182.69,110.567 pad.@221.676,142.809 R25.2 R29.1 | length 77.4
  TOP w0.508: pad.@182.69,110.567 182.738,110.518 182.738,109.738 R29.1@183.068,109.408 184.584,107.892 184.954,107.892 C26.2@185.1,107.746 ; pad.@221.676,142.809 221.676,144.454 R25.2@221.93,144.708
  BOTTOM w0.508: pad.@182.69,110.567 184.322,110.567 187.469,107.42 214.354,107.42 221.676,114.742 pad.@221.676,142.809
NetC27_1: C27.1 pad.@181.253,110.638 pad.@227.518,156.398 R28.2 R30.1 | length 95.9
  TOP w0.508: C27.1@178.75,110.424 179.766,110.424 R30.1@180.782,109.408 R30.1@180.905,109.531 ; pad.@227.518,156.398 R28.2@227.518,158.424
  TOP w0.8: R30.1@180.905,109.531 181.032,109.658 181.032,110.417 pad.@181.253,110.638
  BOTTOM w0.508: pad.@181.253,110.638 182.229,109.662 184.211,109.662 187.131,106.742 214.731,106.742 222.408,114.419 222.408,141.382 227.518,146.492 pad.@227.518,156.398
NetC29_2: C29.2 PC1.A PC2.E R46.1 | length 14.2
  TOP w1.27: PC2.E@30.668,65.593 30.717,65.544 30.717,63.797 31.461,63.053 34.351,63.053 35.318,64.02 35.318,65.417 PC1.A@35.367,65.466 35.367,68.311 35.57,68.514 R46.1@35.57,70.546 R46.1@35.57,70.8
  BOTTOM w1: PC2.E@30.668,65.339 PC2.E@30.793,65.464
NetC32_1: C32.1 CN10.5 EC8.2 IC8.21 | length 43.8
  TOP w1.27: CN10.5@96.073,39.103 102.175,39.103 111.978,29.301 ; IC8.21@117.536,36.247 117.536,32.446 116.281,31.191 116.281,30.937 C32.1@116.266,30.922 C32.1@115.674,30.33 ; IC8.21@117.536,36.637 IC8.21@117.536,37.288 ; 111.978,29.301 112.994,28.285 ; 111.978,29.301 112.012,29.334 114.679,29.334 ; 112.994,28.285 114.409,26.869 114.497,26.869 114.674,26.692 EC8.2@114.674,26.604 114.692,26.622 114.692,27.95 115.183,28.441 ; 112.994,28.285 113.629,28.285 113.785,28.441 ; 112.994,28.285 113.15,28.441 113.785,28.441 ; 113.785,28.441 115.183,28.441 ; 113.785,28.441 114.679,29.334 ; 114.679,29.334 C32.1@115.674,30.33 ; 115.183,28.441 115.674,28.932 C32.1@115.674,30.33
NetC32_2: C32.2 EC8.1 IC8.22 | length 10.8
  TOP w0.508: EC8.1@116.874,26.604 116.874,26.704 118.755,28.585 C32.2@118.755,30.922 118.788,30.955 118.788,36.619 IC8.22@118.806,36.637
NetC33_1: C33.1 CN10.3 EC9.2 IC8.26 | length 48.9
  TOP w1.27: IC8.26@126.426,37.145 126.426,31.43 127.061,30.795 EC9.2@127.061,26.604
  BOTTOM w1.27: CN10.3@96.073,31.303 100.284,31.303 110.526,21.061 120.121,21.061 123.251,24.191 125.664,24.191 127.017,25.544 127.017,26.56 EC9.2@127.061,26.604
NetC33_2: C33.2 EC9.1 IC8.25 | length 10.6
  TOP w0.508: EC9.1@124.861,26.604 124.861,28.566 124.318,29.109 124.318,31.049 125.206,31.937 IC8.25@125.206,36.637
NetC34_1: C34.1 CN10.1 EC10.2 IC8.30 | length 56.1
  TOP w1.27: CN10.1@97.448,23.203 99.589,21.062 135.291,21.062 136.035,21.806 EC10.2@136.035,26.604 136.035,30.914 135.885,31.064 135.885,32.639 133.919,34.605 133.919,37.272
NetC34_2: C34.2 EC10.1 IC8.29 | length 10.5
  TOP w0.508: IC8.29@132.606,36.637 132.606,33.862 133.411,33.057 133.411,29.05 133.835,28.626 EC10.1@133.835,26.604
NetC47_1: C47.1 IC1.2 R110.2 R111.1 | length 6.2
  TOP w0.254: IC1.2@143.754,65.974 146.362,65.974 146.489,66.101 ; R110.2@146.489,66.609 146.489,66.101 ; R111.1@147.986,64.941 147.924,64.879 147.899,64.904 146.359,64.904 146.489,65.035 146.489,66.101
NetC47_2: C47.2 IC1.1 pad.@142.801,55.781 pad.@144.346,64.049 R109.1 R111.2 | length 15.1
  TOP w0.254: pad.@142.801,55.781 143.665,55.781 R109.1@143.682,55.798 ; IC1.1@143.754,64.704 144.255,64.704 IC1.1@144.41,64.704 ; pad.@144.346,64.049 144.988,64.049 145.533,63.504 147.949,63.504 R111.2@147.986,63.541
  TOP w0.508: pad.@142.801,55.781 pad.@142.817,55.798 ; R109.1@143.682,55.798 R109.1@143.698,55.814 ; IC1.1@144.255,64.704 144.298,64.661 144.298,64.097 pad.@144.346,64.049
  BOTTOM w0.254: pad.@142.801,55.781 144.346,57.327 pad.@144.346,64.049
NetC49_1: C49.1 CN5.5 pad.@32.065,24.445 R71.1 R72.2 | length 18.7
  TOP w0.254: pad.@32.065,24.445 35.24,27.62 41.209,27.62 R72.2@44.003,30.414 46.035,30.414 C49.1@46.162,30.541 48.067,30.541 R71.1@48.194,30.414
NetC50_1: C50.1 CN5.3 R73.1 R74.2 | length 19.7
  TOP w0.254: CN5.3@37.145,24.445 38.555,25.855 42.873,25.855 45.4,28.382 48.194,28.382 49.972,30.16 R74.2@50.226,30.16 ; R74.2@50.226,30.414 52.131,30.414 C50.1@52.258,30.541 54.341,30.541 R73.1@54.417,30.465
NetC51_1: C51.1 CN5.1 R75.1 R76.2 | length 21
  TOP w0.254: CN5.1@42.225,24.445 45.654,27.874 48.575,27.874 49.972,29.271 55.377,29.271 R76.2@56.567,30.461 58.528,30.461 58.608,30.541 58.616,30.533 58.674,30.475 R75.1@60.697,30.475
NetC52_1: C52.1 CN8.3 R77.1 R78.2 | length 19.2
  TOP w0.254: CN8.3@50.226,24.445 53.274,27.493 54.417,27.493 56.195,29.271 61.529,29.271 C52.1@62.672,30.414 ; C52.1@62.796,30.63 62.826,30.6 62.962,30.464 R77.1@64.861,30.464 R78.2@66.99,30.465 R78.2@66.99,30.465
NetC53_1: C53.1 CN8.1 R79.1 R80.2 | length 20
  TOP w0.254: CN8.1@55.306,24.445 57.592,26.731 65.466,26.731 R80.2@68.895,30.16 ; R80.2@69.149,30.414 R79.1@71.181,30.414 ; R79.1@71.268,30.493 73.038,30.493 C53.1@73.213,30.668
NetC54_1: C54.1 C92.2 CN_COMP_U.1 CN_COMP_U.2 EC11.2 IC10.6 pad.@180.528,69.784 pad.@181.798,67.879 pad.@182.941,65.593 pad.@183.99,59.269 Q2.3 Q3.2 R121.2 ZD5.1 | length 245.7
  TOP w0.508: Q2.3@182.052,51.869 182.12,51.937 184.906,51.937 R121.2@184.973,52.004 ; pad.@183.99,59.269 183.99,59.201 184.196,58.994 184.196,58.318 C92.2@184.592,57.922 184.988,58.318 184.988,59.039 185.881,59.932 ZD5.1@185.881,60.132 186.167,60.418 C54.1@186.167,62.545 186.167,68.819 187.243,69.895 187.402,69.895 188.148,70.641 EC11.2@188.148,71.441 ; EC11.2@188.275,71.695 188.402,71.822 188.402,74.864 192.77,79.232 192.77,80.813 191.866,81.717 IC10.6@191.866,82.632
  TOP w2.54: 179.512,69.563 Q3.2@179.512,71.8 181.752,69.56 ; pad.@180.528,69.784 179.569,69.219 179.766,69.022 181.354,67.435 183.195,65.593 183.195,68.117 181.752,69.56 ; 181.693,69.56 181.752,69.56
  BOTTOM w0.508: pad.@183.99,59.269 183.99,54.892 184.533,54.35
  BOTTOM w2.54: 152.588,39.177 155.954,42.543 159.129,42.543 ; 155.763,39.177 156.208,39.622 159.129,42.543 ; CN_COMP_U.1@158.049,37.78 158.049,37.849 159.287,39.087 159.287,39.149 160.775,40.636 181.797,40.636 ; Q2.3@182.052,51.869 184.533,54.35 185.616,55.433 186.37,55.433 ; Q2.3@182.15,51.967 182.187,52.004 184.846,52.004 ; 182.433,64.323 180.909,64.323 ; 182.624,41.463 181.797,40.636 ; 183.132,63.625 186.37,60.386 ; 187.386,46.289 187.386,44.003 184.019,40.636 ; 189.737,52.004 189.737,61.575 188.656,62.656 ; 159.129,42.543 182.624,42.543 186.37,46.289 186.37,50.099 ; 177.734,67.498 180.909,64.323 ; 177.734,67.498 177.734,70.022 Q3.2@179.512,71.8 ; 177.734,67.498 177.734,64.323 180.909,64.323 ; Q3.2@179.512,71.8 188.656,62.656 ; Q3.2@179.512,71.8 179.512,68.641 183.83,64.323 184.846,64.323 186.37,62.799 186.37,60.386 ; 181.797,40.636 184.019,40.636 ; 184.019,40.636 185.289,40.636 188.656,44.003 188.656,52.004 ; 184.846,52.004 186.37,52.004 ; 184.846,52.004 184.846,51.623 186.37,50.099 ; 186.37,50.099 186.37,52.004 ; 186.37,52.004 186.37,55.433 ; 186.37,52.004 188.656,52.004 ; 186.37,55.433 186.37,60.386 ; 188.656,52.004 188.656,62.656
NetC54_2: C54.2 D15.2 EC11.1 IC10.8 ZD5.2 | length 27.7
  TOP w0.508: EC11.1@188.148,65.841 188.656,65.333 C54.2@188.656,62.545 188.656,60.513 ZD5.2@189.037,60.132 ; EC11.1@188.656,66.559 188.894,66.797 189.612,66.797 190.688,67.873 190.688,75.21 194.385,78.906 194.385,82.668 IC10.8@194.371,82.682 D15.2@197.038,82.683 D15.2@197.038,82.683
NetC59_1: C59.1 pad.@181.268,82.257 Q3.1 R122.1 R123.1 R124.1 | length 20.7
  TOP w0.508: pad.@181.268,82.257 181.268,83.98 R122.1@181.29,84.002 181.499,84.211 C59.1@183.703,84.211 R124.1@185.862,84.211 187.756,82.317 187.756,82.008 188.302,81.462 R123.1@188.402,81.462
  BOTTOM w0.508: Q3.1@176.972,74.348 176.972,79.182 178.75,80.96 180.02,80.96 181.268,82.208 pad.@181.268,82.257
NetC60_1: C60.1 C93.2 CN_COMP_V.1 CN_COMP_V.2 EC13.2 IC12.6 pad.@198.308,71.816 pad.@200.299,70.176 pad.@202.118,68.387 pad.@202.372,66.101 pad.@202.903,59.496 Q4.3 Q5.2 R128.2 ZD6.1 | length 367
  TOP w0.508: 156.017,30.922 156.017,31.557 ; Q4.3@200.848,51.869 201.106,52.127 203.308,52.127 R128.2@203.566,52.385 ; pad.@202.903,59.496 202.903,59.427 203.041,59.289 203.041,58.3 C93.2@203.437,57.904 204.37,58.836 204.37,59.975 ZD6.1@204.657,60.262 205.09,60.695 C60.1@205.09,62.799 205.09,68.908 206.944,70.762 EC13.2@206.944,71.562 207.233,71.851 IC12.6@207.233,81.836 ; EC13.2@206.765,70.28 EC13.2@207.426,70.28
  TOP w1.6: pad.@198.535,72.224 198.535,71.94 pad.@200.299,70.176 202.103,68.372 202.372,68.103 pad.@202.372,66.101
  TOP w2.54: Q5.2@198.308,71.8 pad.@198.308,71.816
  BOTTOM w0.508: pad.@202.88,59.473 pad.@202.903,59.496 202.903,55.791 203.769,54.925
  BOTTOM w2.54: CN_COMP_V.1@158.049,31.049 168.717,31.049 172.273,27.493 ; 158.303,29.144 168.844,29.144 170.495,27.493 ; 158.43,32.7 170.368,32.7 ; 202.697,67.308 203.115,66.937 203.626,66.482 ; 203.071,64.831 199.578,64.831 199.578,65.339 198.308,66.609 ; 203.769,53.782 205.547,53.782 ; 170.368,32.7 173.289,32.7 176.21,29.779 ; 170.368,32.7 173.289,29.779 176.21,29.779 ; 170.495,27.493 172.273,27.493 ; 170.495,27.493 172.019,25.969 202.535,25.969 204.059,27.493 ; 172.273,27.493 204.059,27.493 ; 176.21,29.779 201.229,29.779 ; 198.308,66.609 198.308,69.149 ; 198.308,66.609 198.308,63.815 198.721,63.402 203.325,63.402 205.547,61.18 ; 198.308,69.149 Q5.2@198.308,71.8 200.975,69.133 ; 198.308,69.149 200.975,66.482 200.975,69.133 ; 200.975,69.133 201.92,68.189 203.626,66.482 ; 201.229,29.779 205.547,34.097 ; 201.229,29.779 203.261,29.779 ; 203.261,29.779 205.547,32.065 205.547,34.097 ; 203.261,29.779 205.197,29.779 207.325,31.907 ; 203.626,66.482 205.547,64.561 ; 204.059,27.493 207.325,30.759 ; 205.547,34.097 205.547,50.635 ; 205.547,50.635 205.547,53.782 ; 205.547,50.635 204.313,51.869 Q4.3@200.848,51.869 200.848,52.004 203.769,54.925 205.547,56.703 ; 205.547,53.782 205.547,56.703 ; 205.547,56.703 205.547,61.18 ; 205.547,61.18 205.547,64.561 ; 205.547,64.561 207.325,62.783 ; 207.325,30.759 208.437,31.871 208.437,61.671 207.325,62.783 ; 207.325,30.759 207.325,31.907 ; 207.325,31.907 207.325,62.783
NetC60_2: C60.2 D18.2 EC13.1 IC12.8 ZD6.2 | length 30.5
  TOP w0.508: EC13.1@206.198,67.508 206.309,67.397 EC13.1@206.309,66.895 ; EC13.1@207.69,67.462 206.944,66.716 EC13.1@206.944,65.962 ; ZD6.2@207.759,60.516 ZD6.2@208.013,60.262 ; ZD6.2@207.813,60.262 207.579,60.496 C60.2@207.579,62.799 207.579,65.327 EC13.1@206.944,65.962 ; D18.2@212.659,82.683 D18.2@212.659,82.683 IC12.8@209.738,82.682 209.738,78.593 209.181,78.036 209.181,66.78 208.884,66.482 207.464,66.482 EC13.1@206.944,65.962
NetC61_2: C61.2 R106.1 | length 5.2
  TOP w2.54: C61.2@112.677,131.011 R106.1@112.677,136.186
NetC62_2: C62.2 R104.2 R105.2 | length 12.4
  TOP w1: C62.2@167.447,122.429 C62.2@167.623,122.429 ; R105.2@171.49,121.208 171.84,121.558 R105.2@171.84,122.108 ; R105.2@171.495,123.414 171.84,123.759
  TOP w2: C62.2@167.32,122.429 C62.2@167.447,122.429 ; C62.2@167.623,122.429 170.51,122.429 ; R105.2@171.495,123.414 170.51,122.429 ; R105.2@171.84,121.558 171.565,121.833 170.969,122.429 ; R105.2@171.84,122.108 R105.2@171.84,122.279 ; R104.2@171.84,125.791 171.84,123.759 R105.2@171.84,122.279 ; 170.51,122.429 170.969,122.429 ; 170.969,122.429 171.69,122.429 R105.2@171.84,122.279
NetC66_1: C66.1 IC1.6 R113.2 R114.1 R116.2 | length 7.8
  TOP w0.254: R114.1@132.903,65.082 132.953,65.082 133.458,64.577 C66.1@134.489,64.577 134.489,64.627 135.616,65.754 135.616,65.955 R113.2@135.889,66.228 135.889,67.244 ; R116.2@135.889,67.879 135.889,67.244 ; IC1.6@138.054,67.244 135.889,67.244
NetC66_2: C66.2 IC1.7 R112.1 R117.2 | length 13.7
  TOP w0.254: R112.1@132.901,68.179 131.729,68.179 131.302,67.752 R117.2@131.252,67.752 131.202,67.752 130.497,67.047 130.497,65.586 132.395,63.688 135.062,63.688 135.616,64.242 135.616,64.304 C66.2@135.889,64.577 135.889,64.627 137.236,65.974 IC1.7@138.054,65.974
NetC75_1: C75.1 C95.2 CN_COMP_W.1 CN_COMP_W.2 EC14.2 IC13.6 pad.@216.85,71.8 pad.@218.709,70.465 pad.@220.307,68.864 pad.@220.914,65.847 pad.@221.442,58.948 pad.@223.2,32.192 pad.@223.2,33.716 pad.@223.196,35.223 pad.@224.654,35.512 pad.@224.703,33.97 pad.@224.724,32.446 pad.@226.123,35.79 pad.@226.178,34.199 pad.@226.248,32.7 pad.@227.64,35.995 pad.@227.797,32.761 pad.@227.797,34.412 Q6.3 Q7.2 R139.2 ZD7.1 | length 429.1
  TOP w0.508: 157.387,21.627 157.792,22.032 ; Q6.3@219.39,51.869 219.458,51.937 222.802,51.937 R139.2@222.87,52.004 ; pad.@221.442,58.948 221.442,58.918 C95.2@222.565,57.795 223.485,58.715 223.485,59.836 ZD7.1@223.781,60.132 ; IC13.6@222.219,82.632 222.219,80.544 225.994,76.769 225.994,70.774 223.708,68.488 223.708,63.866 C75.1@225.029,62.545 223.964,61.481 223.964,60.496 ZD7.1@223.462,59.994
  TOP w1.6: pad.@217.116,72.224 217.116,72.058 pad.@218.709,70.465 220.308,68.866 220.914,68.26 pad.@220.914,65.847
  TOP w2.54: 155.89,23.556 156.268,23.556 ; CN_COMP_W.1@158.176,23.493 216.279,23.493 226.123,33.337 226.123,35.512 pad.@226.123,35.79 ; 158.684,24.826 165.796,24.826 166.812,25.842 215.707,25.842 ; 159.343,21.627 217.715,21.627 227.64,31.552 227.64,35.755 227.52,35.875 223.835,35.875 pad.@223.835,33.97 ; 216.596,25.842 215.707,25.842 ; pad.@216.85,71.8 pad.@216.85,71.816 ; 223.835,33.081 pad.@223.835,33.97 ; pad.@224.703,33.97 pad.@223.835,33.97 ; 215.707,25.842 pad.@223.835,33.97
  BOTTOM w0.508: 221.252,54.587 221.442,54.397 ; pad.@221.442,58.948 221.442,54.397 ; 221.68,54.159 221.442,54.397
  BOTTOM w2.54: Q6.3@219.39,51.869 Q6.3@219.398,51.877 ; 223.2,55.679 221.68,54.159 Q6.3@219.398,51.877 ; pad.@223.545,32.446 pad.@223.581,32.446 ; pad.@225.867,33.843 225.867,35.512 225.867,62.783 ; 216.85,66.101 218.755,66.101 221.676,63.18 ; 216.85,66.101 216.85,69.149 ; 216.85,66.101 216.85,64.668 218.338,63.18 220.66,63.18 ; 216.85,69.149 222.248,63.752 ; 216.85,69.149 Q7.2@216.85,71.8 225.867,62.783 ; Q6.3@219.398,51.877 221.93,51.877 ; 220.66,63.18 223.835,60.005 ; 220.66,63.18 221.676,63.18 ; 221.676,63.18 222.248,63.752 ; 221.93,51.877 223.581,50.226 ; 221.93,51.877 223.073,51.877 ; 222.248,63.752 223.835,62.164 223.835,60.005 ; 223.073,51.877 223.581,52.385 223.581,50.226 ; 223.073,51.877 223.073,53.147 223.835,53.909 223.835,60.005 ; pad.@223.581,32.446 223.581,35.512 223.581,50.226 ; pad.@223.581,32.446 pad.@224.724,32.446 226.121,32.446 227.391,33.716 227.391,61.259 225.867,62.783
NetC75_2: C75.2 D22.2 EC14.1 IC13.8 ZD7.2 | length 30.8
  TOP w0.508: IC13.8@224.724,82.357 224.724,80.96 228.915,76.769 228.915,67.752 228.28,67.117 226.74,67.117 225.994,66.371 225.994,65.174 227.509,63.659 227.509,62.554 C75.2@227.518,62.545 227.518,61.094 ZD7.2@226.756,60.332 ; IC13.8@224.724,82.399 IC13.8@224.724,82.653 ; IC13.8@224.724,82.682 IC13.8@224.724,82.653 ; ZD7.2@226.629,60.132 ZD7.2@226.629,60.332 ; ZD7.2@226.683,60.386 ZD7.2@226.937,60.132 ; D22.2@227.772,82.683 227.7,82.611 224.767,82.611 IC13.8@224.724,82.653
NetC77_1: C77.1 D9.1 D10.2 IC5.3 pad.@179.68,105.633 pad.@179.503,102.395 R30.2 R31.2 R32.1 | length 94.7
  TOP w0.254: R31.2@112.202,87.818 113.607,87.818 114.369,88.58 115.758,88.58 117.917,90.739 121.346,90.739 122.103,91.496 163.116,91.496 169.937,98.317 177.816,98.317 180.456,100.957 180.506,100.957 180.779,101.23 R32.1@180.779,101.28 ; D10.2@176.083,109.735 D10.2@176.264,109.916 176.137,110.043 D9.1@176.137,112.583 ; pad.@179.503,102.395 179.552,102.346 pad.@179.6,102.298 ; R30.2@180.35,106.487 R30.2@180.782,106.919 ; R32.1@180.517,101.542 180.583,101.476 R32.1@180.779,101.28 ; R32.1@180.779,101.33 R32.1@180.779,101.28 ; C77.1@180.782,104.898 180.813,104.867 C77.1@180.844,104.836
  TOP w0.508: D10.2@176.083,109.735 176.083,107.249 176.827,106.505 177.899,106.505 IC5.3@177.917,106.487 179.258,106.487 ; pad.@179.552,102.346 179.552,101.875 179.951,101.476 180.583,101.476 180.633,101.476 R32.1@180.779,101.33 ; pad.@179.68,105.633 179.639,105.674 179.639,106.106 ; R30.2@180.35,106.487 179.995,106.487 ; R30.2@180.782,106.919 180.813,106.888 C77.1@180.813,104.867 ; 179.258,106.487 179.639,106.487 ; 179.258,106.487 179.639,106.106 ; 179.639,106.106 179.639,106.131 ; 179.639,106.131 179.995,106.487 ; 179.639,106.131 179.639,106.487 ; 179.639,106.487 179.995,106.487
  BOTTOM w0.508: pad.@179.503,102.395 179.503,102.464 179.639,102.599 179.639,105.591 pad.@179.68,105.633
NetC77_2: C77.2 D9.2 D10.1 IC5.2 R29.2 R33.1 | length 20.9
  TOP w0.5: D9.2@172.981,112.583 173.108,112.456 D10.1@173.108,109.916 ; D10.1@173.162,109.662 175.092,107.732 175.092,106.335 176.21,105.217 IC5.2@177.917,105.217 178.667,105.217 180.064,103.82 181.925,103.82 ; C77.2@182.094,104.686 C77.2@182.212,104.803 ; R33.1@182.179,102.804 182.212,102.836 182.212,103.328 ; R29.2@183.068,106.919 182.244,106.095 C77.2@182.244,104.836 C77.2@182.212,104.803 ; 181.925,103.82 182.212,103.82 ; 181.925,103.82 181.925,104.025 182.212,104.312 ; 181.925,103.82 181.925,103.615 182.212,103.328 ; 182.212,103.328 182.212,103.82 ; 182.212,103.82 182.212,104.312 ; 182.212,104.312 C77.2@182.212,104.803
NetC79_2: C79.2 D25.2 IC14.1 R102.1 R103.2 | length 10.4
  TOP w0.254: D25.2@170.492,86.205 171.165,85.532 171.184,85.532 D25.2@171.257,85.532 D25.2@171.511,85.278 ; IC14.1@173.754,85.84 173.924,85.67 IC14.1@173.924,85.278
  TOP w0.508: R102.1@170.492,87.691 170.638,87.545 170.638,86.078 D25.2@171.184,85.532 ; D25.2@171.511,85.278 171.638,85.151 IC14.1@173.881,85.151 ; IC14.1@173.924,85.278 173.881,85.235 IC14.1@173.881,85.151 ; R103.2@175.448,83.503 C79.2@173.797,83.503 173.881,83.587 IC14.1@173.881,85.151
NetC80_1: C80.1 COM.1 COM.2 R107.2 | length 25.2
  TOP w1.27: R107.2@22.54,76.134 22.604,76.198 22.604,79.373 COM.2@22.667,79.436 COM.1@22.667,84.516 22.915,84.764 22.915,88.086 C80.1@23.061,88.232 C80.1@23.207,88.086 ; R107.2@22.667,75.815 22.763,75.911 R107.2@22.8,75.948
  BOTTOM w1.27: R107.2@22.54,76.134 22.604,76.198 22.604,79.373 COM.2@22.667,79.436 COM.1@22.667,84.516 22.915,84.764 22.915,88.086 C80.1@23.061,88.232 C80.1@23.207,88.086
NetC81_2: C81.2 IC8.4 R51.1 R52.1 | length 8
  TOP w0.254: IC8.4@130.406,50.437 130.406,53.825 130.49,53.909 132.725,53.909 132.776,53.96 134.884,53.96 C81.2@134.935,53.909
NetC82_1: C82.1 R134.1 | length 3.5
  TOP w1.5: R134.1@75.248,71.435 78.566,71.435 78.633,71.502 C82.1@78.674,71.502
NetC84_1: C84.1 IC8.9 R53.2 R54.1 | length 22.6
  TOP w0.508: IC8.9@125.406,50.437 125.424,50.419 125.424,48.18 127.188,46.416 132.615,46.416 135.696,49.497 136.067,49.497 C84.1@136.463,49.893 ; C84.1@136.815,49.87 138.77,49.87 R53.2@138.872,49.972 137.983,50.861 137.983,53.325 R54.1@137.094,54.214
NetC85_1: C85.1 D20.2 EC19.1 IC8.20 IC8.27 IC8.28 R53.1 R57.1 R59.2 R60.2 R61.2 R62.2 | length 89.4
  TOP w0.508: R53.1@141.361,49.972 141.425,50.036 143.304,50.036 R57.1@143.368,50.099 143.368,47.867 143.314,47.813 143.207,47.706 R62.2@143.154,47.653
  TOP w1: D20.2@142.555,21.905 142.555,25.598 143.276,26.319 EC19.1@143.276,26.604 143.36,26.688 143.36,31.981 143.444,32.065 143.379,32.13 143.379,39.493 R59.2@143.314,39.558
  TOP w2: 114.438,36.662 114.438,41.286 117.536,44.384 127.193,44.384 ; 129.511,36.662 129.511,41.119 ; R62.2@143.154,47.653 141.412,47.653 ; R59.2@143.314,39.558 R61.2@143.314,44.892 R61.2@143.314,45.751 ; R62.2@143.314,47.813 R61.2@143.314,45.751 ; 127.193,44.384 132.522,44.384 132.649,44.257 ; 127.193,44.384 128.524,43.053 ; 128.524,43.053 129.511,44.04 ; 128.524,43.053 129.511,42.066 ; 129.511,41.119 132.649,44.257 ; 129.511,41.119 129.511,42.066 ; 129.511,42.066 129.511,44.04 ; 129.511,44.04 129.728,44.257 132.649,44.257 ; 132.649,44.257 136.045,47.653 141.412,47.653 ; 141.412,47.653 R61.2@143.314,45.751
NetC87_1: C87.1 CN9.1 R142.1 R144.2 | length 11.8
  TOP w0.254: C87.1@95.184,74.788 R144.2@97.089,74.788 R144.2@97.089,74.587 ; CN9.1@95.565,68.514 97.089,70.038 R144.2@97.089,74.587 ; R144.2@97.038,74.587 R144.2@97.089,74.587 ; R142.1@99.248,73.086 99.075,73.259 98.366,73.259 97.612,74.013 97.612,74.265 97.29,74.587 R144.2@97.089,74.587
NetC91_2: C91.2 IC14.3 pad.@175.981,84.807 R146.1 R147.2 | length 10.1
  TOP w0.254: IC14.3@175.824,85.278 175.824,84.964 pad.@175.981,84.807 ; R147.2@176.841,83.761 176.903,83.699 R147.2@177.099,83.503 177.163,83.567 R147.2@177.165,83.569 ; C91.2@178.687,83.567 179.879,84.759 179.879,87.909 179.385,88.403 R146.1@179.385,88.453
  TOP w0.508: 175.824,84.964 175.824,84.872 176.903,83.793 176.903,83.699 176.903,83.649 177.049,83.503 R147.2@177.099,83.503 ; R147.2@177.163,83.567 C91.2@178.687,83.567
NetC92_1: C92.1 Q2.1 R91.1 R120.1 R121.1 | length 17.3
  TOP w0.508: Q2.1@176.972,51.869 177.107,52.004 179.131,52.004 180.655,53.528 182.687,53.528 C92.1@184.592,55.433 185.983,55.433 186.359,55.057 186.359,54.957 R120.1@186.905,54.411 187.005,54.411 187.375,54.041 187.375,52.091 R121.1@187.462,52.004 ; R121.1@187.208,52.004 R121.1@187.208,52.131
  TOP w0.8: R91.1@186.999,49.591 187.104,49.696 187.104,52.026 R121.1@187.208,52.131
NetC93_1: C93.1 Q4.1 R126.1 R127.1 R128.1 | length 17
  TOP w0.508: Q4.1@195.768,51.869 195.816,51.869 197.174,53.226 199.911,53.226 200.721,54.036 202.058,54.036 C93.1@203.437,55.414 205.079,55.414 205.701,54.792 R127.1@205.801,54.792 206.055,54.538 R128.1@206.055,52.385 206.055,50.105 R126.1@205.795,49.845 ; R127.1@206.209,54.668 R127.1@206.309,54.668
NetC94_1: C94.1 Q5.1 R129.1 R130.1 R131.1 | length 18.9
  TOP w0.508: Q5.1@195.768,74.348 Q5.1@195.938,74.348 ; Q5.1@196.118,74.348 Q5.1@195.938,74.348 ; R131.1@201.42,84.834 R131.1@201.356,84.897 ; R130.1@203.261,87.304 R129.1@200.57,87.304 ; Q5.1@195.938,74.348 C94.1@198.359,76.769 201.356,79.766 R131.1@201.356,84.897 ; R129.1@200.57,87.304 200.47,87.304 R129.1@200.467,87.307 200.567,87.307 R129.1@200.57,87.304 ; R129.1@200.57,87.304 201.356,86.518 R131.1@201.356,84.897
NetC95_1: C95.1 Q6.1 R137.1 R138.2 R139.1 | length 17.5
  TOP w0.508: Q6.1@214.31,51.869 214.768,51.869 215.792,52.893 217.866,52.893 218.755,53.782 221.041,53.782 C95.1@222.565,55.306 ; C95.1@222.817,55.052 223.452,54.417 225.232,54.417 225.244,54.429 225.613,54.06 225.613,51.946 R139.1@225.593,51.926 ; R137.1@225.359,49.458 R139.1@225.359,51.946
NetC96_1: C96.1 Q7.1 R140.1 R141.2 R143.1 | length 18.2
  TOP w0.508: Q7.1@214.31,74.348 214.557,74.595 214.557,75.568 C96.1@215.885,76.896 216.215,77.226 216.215,83.83 R143.1@217.485,85.1 216.371,86.215 R141.2@216.371,87.151 ; R140.1@215.58,90.479 215.58,87.942 R141.2@215.831,87.691 R141.2@216.371,87.151 ; R141.2@216.377,87.145 R141.2@216.371,87.151
NetC97_2: C97.2 C100.2 IC8.6 | length 9.3
  TOP w0.254: C100.2@127.823,59.421 127.823,54.747 C97.2@128.153,54.417 ; C97.2@128.161,54.483 128.19,54.454 128.406,54.238 IC8.6@128.406,50.437
NetC99_1: C99.1 FB2.2 IC11.24 | length 13.1
  TOP w0.254: C99.1@101.903,77.204 103.431,75.677 FB2.2@104.582,75.677 ; FB2.2@104.43,75.525 104.801,75.154 108.102,75.154 108.649,74.607 113.215,74.607 113.218,74.61 113.222,74.606 IC11.24@113.387,74.606
  TOP w0.4: FB2.2@104.278,75.372 104.43,75.525 FB2.2@104.582,75.677
NetC111_2: C111.2 IC7.1 IC7.8 R151.2 | length 10.5
  TOP w0.254: IC7.8@196.601,102.677 198.181,102.677 ; R151.2@198.435,99.248 198.562,99.375 C111.2@198.562,100.896 ; C111.2@198.497,100.831 C111.2@198.562,100.896 ; C111.2@198.667,101.001 C111.2@198.562,100.896 ; IC7.1@202.301,102.677 198.816,102.677 ; 198.181,102.677 198.435,102.677 ; 198.181,102.677 198.181,102.593 198.478,102.296 ; 198.435,102.677 198.816,102.677 ; 198.435,102.677 198.478,102.634 198.478,102.296 ; 198.478,102.296 198.816,102.634 198.816,102.677 ; 198.478,102.296 198.478,101.11 C111.2@198.562,101.026 C111.2@198.562,100.896
NetCN3_2: CN3.2 R36.2 R149.1 | length 17
  TOP w0.254: CN3.2@63.18,23.241 63.18,23.556 67.117,27.493 72.451,27.493 R36.2@75.118,30.16 ; R36.2@75.372,30.414 R149.1@77.404,30.414
NetCN3_3: CN3.3 R35.2 R148.1 | length 20.2
  TOP w0.254: CN3.3@65.72,23.302 65.72,25.369 67.209,26.858 72.705,26.858 75.118,29.271 78.454,29.271 R148.1@79.677,30.494 ; R148.1@79.677,30.414 R35.2@81.722,30.414
NetCN11_1: CN11.1 IC9.13 | length 7.3
  TOP w0.508: CN11.1@24.064,39.177 26.35,41.463 IC9.13@30.418,41.463
NetCN11_2: CN11.2 IC9.12 | length 6.8
  TOP w0.5: IC9.12@29.99,42.733 IC9.12@30.418,42.733
  TOP w0.508: CN11.2@24.064,41.717 25.08,42.733 IC9.12@29.99,42.733
NetCN11_3: CN11.3 IC9.11 | length 7.1
  TOP w0.254: CN11.3@23.429,44.177 23.53,44.076 23.943,44.076 CN11.3@23.991,44.027
  TOP w0.508: CN11.3@24.064,44.257 24.254,44.067 24.793,44.067 24.858,44.003 IC9.11@30.418,44.003
NetCN11_4: CN11.4 IC9.10 pad.@24.064,46.797 | length 7
  TOP w0.254: IC9.10@29.823,45.273 IC9.10@30.418,45.273
  TOP w0.508: pad.@24.064,46.797 25.588,45.273 IC9.10@29.823,45.273
NetCN-VL1_1: CN_VL1.1 CN_VL1.2 RC1.2 RC1.@26.818,113.915 RY2.2 | length 90.6
  TOP w2.54: CN_VL1.2@27.493,101.915 26.731,102.677 RC1.2@26.731,111.502 ; CN_VL1.2@27.897,101.933 27.897,107.013 27.848,107.062 27.848,110.385 27.461,110.773 ; RY2.2@32.974,116.276 29.18,116.276 28.535,115.631 ; RC1.2@26.731,111.502 RC1.2@26.818,111.415 27.461,110.773 ; RC1.2@26.731,111.502 26.731,113.827 RC1.@26.818,113.915 ; RC1.@26.818,113.915 30.603,113.915 ; RC1.@26.818,113.915 28.535,115.631 ; 27.461,110.773 30.603,113.915 ; 28.535,115.631 32.954,115.631 31.238,113.915 30.603,113.915
  BOTTOM w2.54: CN_VL1.2@26.818,102.764 26.818,104.645 ; CN_VL1.2@27.897,101.933 27.897,103.566 ; 26.818,104.645 RC1.2@26.818,111.415 ; 26.818,104.645 27.897,103.566 ; RC1.2@26.818,111.415 28.113,111.415 ; RC1.2@26.818,111.415 26.818,113.091 ; 26.818,113.091 29.358,115.631 ; 26.818,113.091 RC1.@26.818,113.915 26.818,114.143 28.306,115.631 ; 27.897,103.566 27.897,107.013 27.848,107.062 27.848,111.15 28.113,111.415 ; 28.113,111.415 32.329,115.631 ; 28.306,115.631 29.358,115.631 ; 28.306,115.631 28.951,116.276 RY2.2@32.974,116.276 32.329,115.631 ; 29.358,115.631 32.329,115.631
